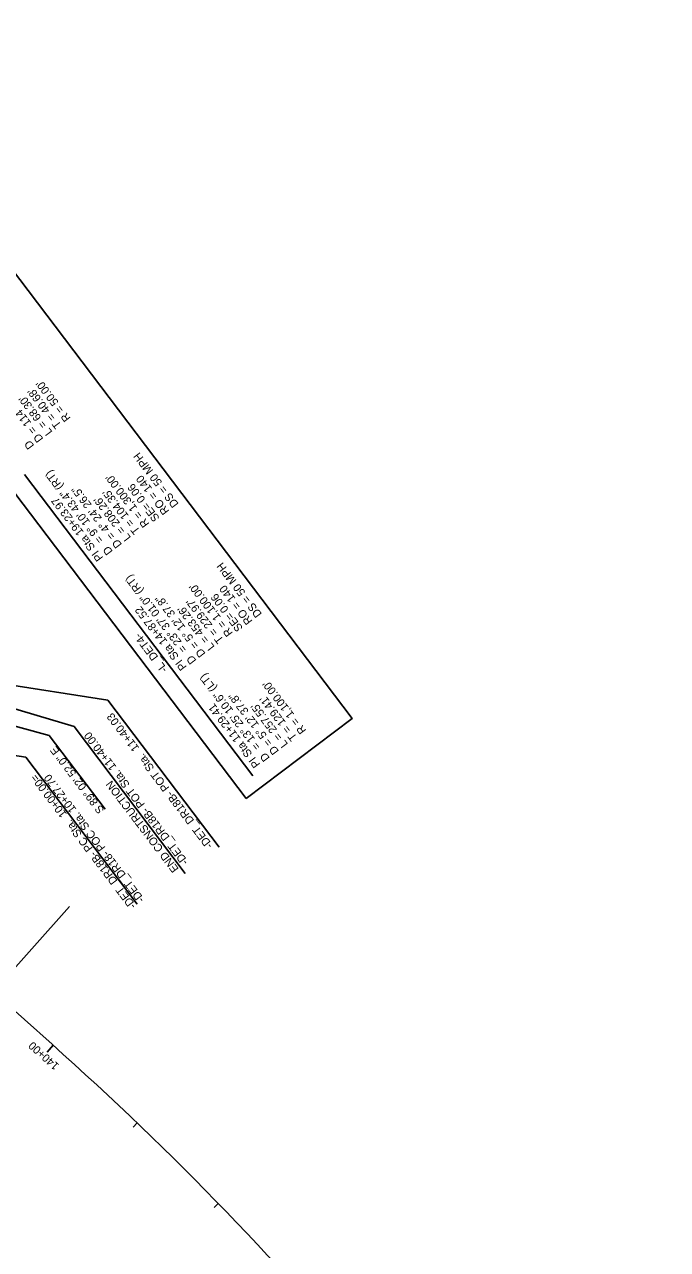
# Model space of a CAD drawing. Extents: x 473658 to 481584, y 489119 to 506230.
# Drawn here: x 477047 to 477609, y 500165 to 501237 of the extents above; entities that cross this region are included whole.
import ezdxf

# ---------------------------------------------------------------- set-up
doc = ezdxf.new("R2010")
doc.units = 0
for name, color, linetype in [('Prop Grid Mask', 7, 'Continuous'), ('Prop Horizontal Alignment', 7, 'Continuous'), ('Prop Horizontal Alignment Curve and Spiral Data', 7, 'Continuous'), ('Prop Horizontal Alignment Direction Label', 7, 'Continuous'), ('Prop Horizontal Alignment Station Label', 7, 'Continuous'), ('Prop Horizontal Alignment Tick Label', 7, 'Continuous'), ('Prop Horizontal Alignment Tick Large', 7, 'Continuous'), ('Prop Horizontal Alignment Tick Small', 7, 'Continuous'), ('Scratch_Level_9', 7, 'Continuous')]:
    doc.layers.add(name, color=color, linetype=linetype)

msp = doc.modelspace()

# ---------------------------------------------------------------- linework, layer by layer
at = {"layer": 'Prop Grid Mask'}
msp.add_lwpolyline([(477240.4, 500559.9), (476603.5, 501401.3), (476696.2, 501471.5), (477333.1, 500630.1)], close=True, dxfattribs=at)
at = {"layer": 'Prop Horizontal Alignment'}
msp.add_line((477070.7, 500345), (476711.1, 500666), dxfattribs=at)
msp.add_arc((475172.8, 498218.8), 2850, 31.2722, 48.2476, dxfattribs=at)
at = {"layer": 'Prop Horizontal Alignment Curve and Spiral Data'}
msp.add_line((477246.2, 500579.9), (477046.7, 500843.4), dxfattribs=at)
at = {"layer": 'Prop Horizontal Alignment Station Label'}
for p, q in [((477068.2, 500615), (476846.8, 500675.8)), ((476903.1, 500679.9), (477119.5, 500646.1)), ((477089.9, 500622.9), (476903.2, 500678.4)), ((477216.8, 500517.5), (477119.5, 500646.1)), ((476786.2, 500633.6), (477047.8, 500596.2)), ((477187.2, 500494.3), (477089.9, 500622.9)), ((477117, 500550.6), (477068.2, 500615)), ((477145.2, 500467.6), (477047.8, 500596.2))]:
    msp.add_line(p, q, dxfattribs=at)
at = {"layer": 'Prop Horizontal Alignment Tick Large'}
msp.add_line((477071.6, 500344.1), (477066.3, 500338.2), dxfattribs=at)
at = {"layer": 'Prop Horizontal Alignment Tick Small'}
for p, q in [((477145, 500276.2), (477141.6, 500272.6)), ((477216, 500205.8), (477212.4, 500202.3))]:
    msp.add_line(p, q, dxfattribs=at)
at = {"layer": 'Scratch_Level_9'}
msp.add_line((476952.8, 500316.2), (477085.9, 500465.4), dxfattribs=at)

# ---------------------------------------------------------------- texts
at = {"layer": 'Prop Horizontal Alignment Curve and Spiral Data'}
for s, rotation, p in [('D = 114%%d 35\' 29.6"', 127.1236, (477063.4, 500874.7)), ("T = 40.68'", 127.1236, (477079.3, 500886.8)), ("R = 50.00'", 127.1236, (477087.3, 500892.8)), ("L = 68.30'", 127.1236, (477071.3, 500880.7)), ('D', 127.1236, (477055.4, 500868.7)), ('DS = 50 MPH', 127.2685, (477181.7, 500817.7)), ('= 9%%d 10\' 43.4" (RT)', 127.1236, (477116.1, 500786.3)), ('RO = 140', 127.2685, (477173.5, 500811.5)), ("R = 1,300.00'", 127.1236, (477156, 500800.3)), ('SE= 0.06', 127.2685, (477165.1, 500805.4)), ('PI Sta 19+23.97', 127.1236, (477115.7, 500770.7)), ('D = 4%%d 24\' 26.5"', 127.1236, (477132.1, 500782.2)), ("L = 208.26'", 127.1236, (477140, 500788.3)), ("T = 104.35'", 127.1236, (477148, 500794.3)), ('D', 127.1236, (477124.1, 500776.2)), ('DS = 50 MPH', 127.2685, (477254.5, 500721.5)), ('= 23%%d 37\' 01.0" (RT)', 127.1236, (477189.2, 500690.7)), ("R = 1,100.00'", 127.1236, (477229.1, 500704.8)), ('RO = 140', 127.2685, (477246.3, 500715.3)), ('D = 5%%d 12\' 37.8"', 127.1236, (477205.2, 500686.7)), ('SE= 0.06', 127.2685, (477237.9, 500709.2)), ('PI Sta 14+87.52', 127.1236, (477188.8, 500675.2)), ("L = 453.26'", 127.1236, (477213.2, 500692.7)), ("T = 229.97'", 127.1236, (477221.1, 500698.8)), ('D', 127.1236, (477197.2, 500680.7)), ('= 13%%d 25\' 10.6" (LT)', 127.1236, (477253.4, 500605.6)), ("R = 1,100.00'", 127.1236, (477293.3, 500619.6)), ('D = 5%%d 12\' 37.8"', 127.1236, (477269.4, 500601.5)), ('PI Sta 11+29.41', 127.1236, (477253, 500590)), ("L = 257.55'", 127.1236, (477277.3, 500607.6)), ("T = 129.41'", 127.1236, (477285.3, 500613.6)), ('D', 127.1236, (477261.4, 500595.5))]:
    msp.add_text(s, height=7, rotation=rotation, dxfattribs=at).set_placement(p)
at = {"layer": 'Prop Horizontal Alignment Direction Label'}
msp.add_text('S 89%%d 02\' 52.0" E', height=7, rotation=127.1236, dxfattribs=at).set_placement((477116.7, 500550))
at = {"layer": 'Prop Horizontal Alignment Station Label'}
for s, rotation, p in [('-L_DET4-', 127.1236, (477172, 500673.1)), ('-DET_DR18B- POT Sta.  11+40.03', 127.1236, (477211.6, 500519.2)), ('-DET_DR18B- POT Sta. 11+40.00', 127.1612, (477190.2, 500504.8)), ('-DET_DR18B- PC Sta.  10+00.00=', 127.1236, (477144.6, 500466.4)), ('-DET_DR18- POC Sta. 10+27.70 ', 127.1236, (477151.9, 500471.9)), ('END CONSTRUCTION', 127.1612, (477181.8, 500498.5))]:
    msp.add_text(s, height=7, rotation=rotation, dxfattribs=at).set_placement(p)
at = {"layer": 'Prop Horizontal Alignment Tick Label'}
msp.add_text('140+00', height=7, rotation=138.2213, dxfattribs=at).set_placement((477077.4, 500326.9))

doc.saveas('drawing.dxf')
